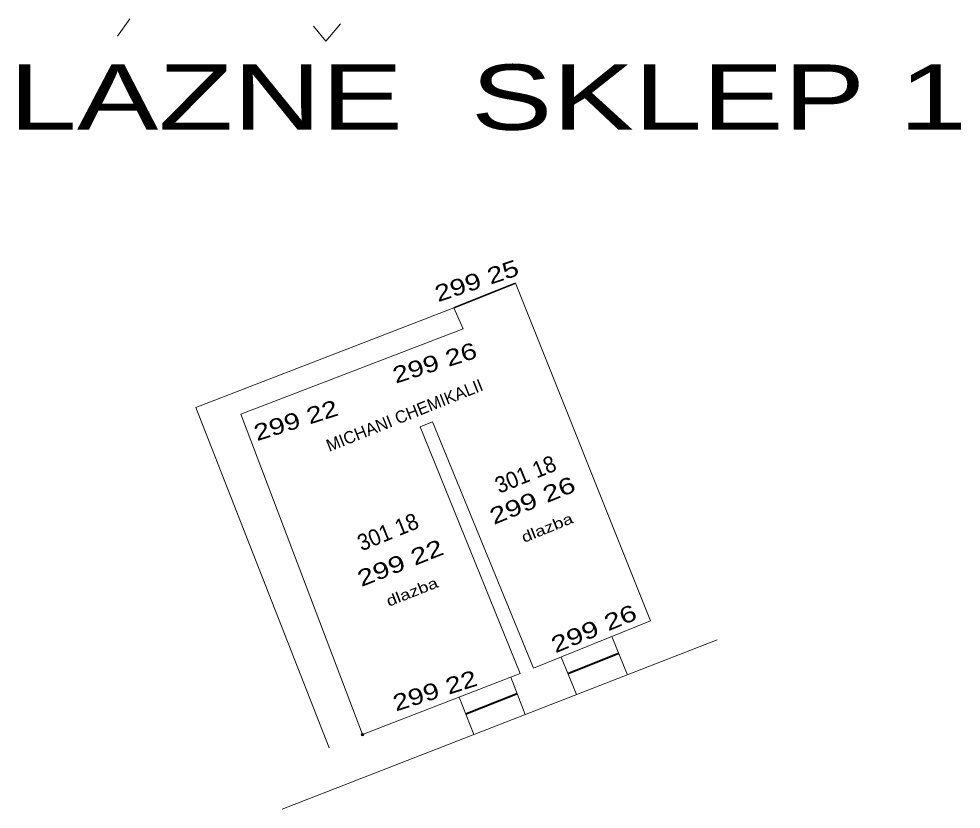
# Model space of a CAD drawing. Extents: x -642923.1 to -642906.9, y -1193255.4 to -1193224.4.
# Drawn here: x -642921.45 to -642907.03, y -1193236.53 to -1193224.44 of the extents above; entities that cross this region are included whole.
import ezdxf
from ezdxf.enums import TextEntityAlignment as Align

# ---------------------------------------------------------------- set-up
doc = ezdxf.new("R2010")
doc.units = 0
doc.header["$LTSCALE"] = 0.08
doc.header["$PDMODE"] = 32
doc.header["$PDSIZE"] = 0.04
for name, color, linetype, lineweight in [('1', 7, 'Continuous', 13), ('13', 7, 'Continuous', 40), ('5', 7, 'Continuous', 13), ('6', 7, 'Continuous', 35), ('8', 7, 'Continuous', 13)]:
    doc.layers.add(name, color=color, linetype=linetype, lineweight=lineweight)
for name, color, linetype in [('3', 7, 'Continuous'), ('40', 7, 'Continuous'), ('41', 7, 'Continuous'), ('53', 7, 'Continuous')]:
    doc.layers.add(name, color=color, linetype=linetype)

msp = doc.modelspace()

# ---------------------------------------------------------------- linework, layer by layer
at = {"layer": '1'}
for p, q in [((-642919.941, -1193224.703), (-642919.751, -1193224.437)), ((-642912.139, -1193234.465), (-642912.372, -1193233.889)), ((-642912.916, -1193234.779), (-642913.149, -1193234.203)), ((-642913.698, -1193235.084), (-642913.92, -1193234.511)), ((-642914.487, -1193235.39), (-642914.709, -1193234.817))]:
    msp.add_line(p, q, dxfattribs=at)
msp.add_lwpolyline([(-642916.943, -1193224.551), (-642916.753, -1193224.779), (-642916.526, -1193224.513)], dxfattribs=at)
at = {"layer": '13'}
for p, q in [((-642913.047, -1193234.455), (-642912.268, -1193234.146)), ((-642914.61, -1193235.072), (-642913.822, -1193234.763))]:
    msp.add_line(p, q, dxfattribs=at)
at = {"layer": '5'}
for p, q in [((-642913.85, -1193228.48), (-642911.78, -1193233.65)), ((-642916.701, -1193235.592), (-642918.743, -1193230.385)), ((-642910.76, -1193233.941), (-642917.42, -1193236.531))]:
    msp.add_line(p, q, dxfattribs=at)
at = {"layer": '6'}
msp.add_line((-642913.85, -1193228.48), (-642914.79, -1193228.86), dxfattribs=at)
at = {"layer": '8'}
for p, q in [((-642918.743, -1193230.385), (-642914.79, -1193228.86)), ((-642916.189, -1193235.391), (-642918.052, -1193230.488)), ((-642915.119, -1193230.602), (-642915.31, -1193230.68)), ((-642913.574, -1193234.375), (-642915.119, -1193230.602)), ((-642915.31, -1193230.68), (-642913.775, -1193234.454)), ((-642911.78, -1193233.65), (-642913.574, -1193234.375)), ((-642913.775, -1193234.454), (-642916.189, -1193235.391))]:
    msp.add_line(p, q, dxfattribs=at)
msp.add_lwpolyline([(-642918.052, -1193230.488), (-642914.647, -1193229.181), (-642914.79, -1193228.86), (-642913.85, -1193228.48)], dxfattribs=at)
msp.add_point((-642916.189, -1193235.391), dxfattribs=at)

# ---------------------------------------------------------------- texts
at = {"layer": '1', "width": 1.4}
msp.add_text('LAZNE  SKLEP 1', height=1, dxfattribs=at).set_placement((-642914.2695, -1193226.135), align=Align.CENTER)
at = {"layer": '3'}
for s, rotation, width, p in [('299 25', 18.443, 1.3, (-642914.40354, -1193228.56308)), ('299 26', 17.638, 1.3, (-642915.04788, -1193229.81861)), ('299 22', 17.638, 1.3, (-642917.17338, -1193230.69968)), ('299 26', 22.35, 1.35, (-642913.54203, -1193231.92047)), ('299 22', 21.634, 1.35, (-642915.56709, -1193232.87878)), ('299 26', 22.629, 1.35, (-642912.6016, -1193233.88305)), ('299 22', 17.638, 1.3, (-642915.04538, -1193234.83568))]:
    msp.add_text(s, height=0.25, rotation=rotation, dxfattribs=dict(at, width=width)).set_placement(p, align=Align.CENTER)
at = {"layer": '40', "width": 1.3}
for rotation, p in [(22.211, (-642913.33262, -1193232.3007)), (21.556, (-642915.40126, -1193233.28151))]:
    msp.add_text('dlazba', height=0.162, rotation=rotation, dxfattribs=at).set_placement(p, align=Align.CENTER)
at = {"layer": '41'}
msp.add_text('MICHANI CHEMIKALII', height=0.188, rotation=21.791, dxfattribs=at).set_placement((-642915.51239, -1193230.59081), align=Align.CENTER)
at = {"layer": '53', "width": 0.95}
for p in [(-642913.64765, -1193231.5226), (-642915.75465, -1193232.4036)]:
    msp.add_text('301 18', height=0.25, rotation=22.162, dxfattribs=at).set_placement(p, align=Align.CENTER)

doc.saveas('drawing.dxf')
